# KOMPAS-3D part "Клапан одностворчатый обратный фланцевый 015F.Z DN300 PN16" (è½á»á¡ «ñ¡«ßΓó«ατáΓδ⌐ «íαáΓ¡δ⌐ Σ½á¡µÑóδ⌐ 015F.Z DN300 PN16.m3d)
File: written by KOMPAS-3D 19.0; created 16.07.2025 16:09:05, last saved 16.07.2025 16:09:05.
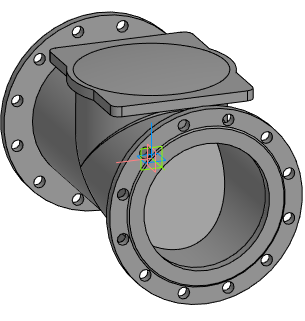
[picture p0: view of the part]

Document properties: Полное имя файла: E:\Dendor Работа Сачек\3D для проектировщиков\5.4 Тип 015F.Z. Клапан одностворчатый обратный фланцевый\stp_Клапан одностворчатый обратный фланцевый 015F.Z PN10_16\Клапан одностворчатый обратный фланцевый 015F.Z DN300 PN16.m3d

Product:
- Part/product: Клапан одностворчатый обратный фланцевый 015F.Z DN300 PN16

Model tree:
1. Операция без истории:1  (labels: Клапан одностворчатый обратный фланцевый 015F.Z DN300 PN16)
2. Операция без истории:2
